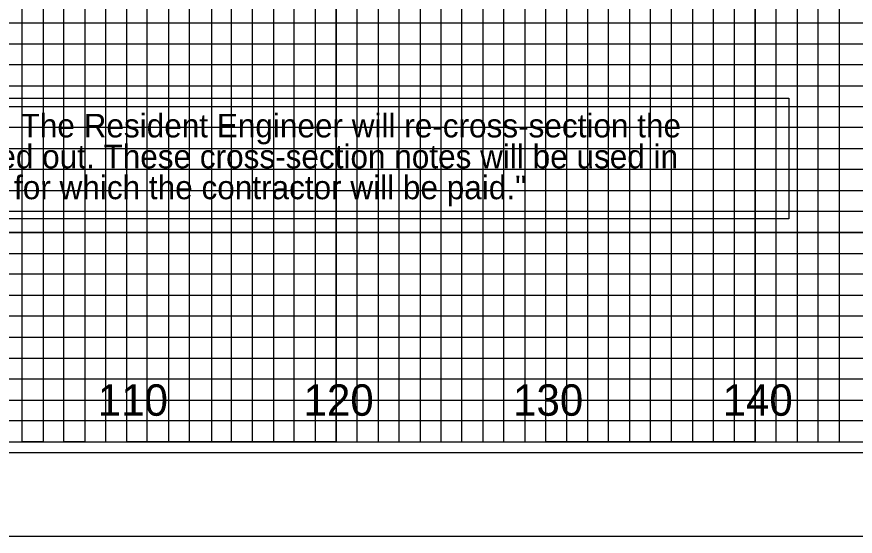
# Model space of a CAD drawing. Extents: x -13 to 371, y -5 to 215.
# Drawn here: x 264.75 to 304.77, y -4.5 to 20.29 of the extents above; entities that cross this region are included whole.
import ezdxf

# ---------------------------------------------------------------- set-up
doc = ezdxf.new("R2010")
doc.units = 0
for name, color, linetype in [('Exist Cross Section Cell', 7, 'Continuous'), ('Exist XS Center Line Elevation Label', 7, 'Continuous'), ('Exist XS Ground Line', 7, 'Continuous'), ('Prop CMT Pvmt Course 2', 7, 'Continuous'), ('Prop CMT Pvmt Course 3', 7, 'Continuous'), ('Prop CMT Pvmt Wedge Surface 2', 7, 'Continuous'), ('Prop CMT Pvmt Wedge Surface 3', 7, 'Continuous'), ('Prop CMT Shld Paved Course 2', 7, 'Continuous'), ('Prop CMT Shld Paved Course 3', 7, 'Continuous'), ('Prop CMT Slope Grass', 7, 'Continuous'), ('Prop CMT Subgrade Earthwork', 7, 'Continuous'), ('Scratch_Level_0', 7, 'Continuous')]:
    doc.layers.add(name, color=color, linetype=linetype)

msp = doc.modelspace()

# ---------------------------------------------------------------- linework, layer by layer
at = {"layer": 'Exist XS Center Line Elevation Label'}
for points in [[(264.99, 205), (264.99, 0), (275, 0), (275, 205)], [(285, 205), (285, 0), (295, 0), (295, 205)], [(0, 5), (320, 5), (320, 15), (0, 15)]]:
    msp.add_lwpolyline(points, dxfattribs=at)
at = {"layer": 'Exist XS Ground Line'}
for p, q in [((270, 0), (270, 205)), ((280, 205), (280, 0)), ((290, 0), (290, 205)), ((300, 205), (300, 0)), ((280, 0), (270, 0)), ((300, 0), (290, 0))]:
    msp.add_line(p, q, dxfattribs=at)
msp.add_lwpolyline([(0, 20), (320, 20), (320, 10), (0, 10)], dxfattribs=at)
at = {"layer": 'Prop CMT Pvmt Course 2'}
for p, q in [((270, 0), (270, 204.687)), ((280, 0), (280, 204.687)), ((290, 0), (290, 204.687)), ((300, 0), (300, 204.687)), ((0, 20), (320, 20)), ((0, 10), (320, 10))]:
    msp.add_line(p, q, dxfattribs=at)
at = {"layer": 'Prop CMT Pvmt Course 3'}
msp.add_line((-13.4, -4.5), (323.3, -4.5), dxfattribs=at)
at = {"layer": 'Prop CMT Pvmt Wedge Surface 2'}
msp.add_lwpolyline([(235.854, 16.408), (301.608, 16.408), (301.608, 10.642), (235.854, 10.642)], close=True, dxfattribs=at)
at = {"layer": 'Prop CMT Shld Paved Course 2'}
msp.add_lwpolyline([(-13.4, -4.5), (323.3, -4.5), (323.3, 214.5), (-13.4, 214.5)], close=True, dxfattribs=at)
at = {"layer": 'Prop CMT Shld Paved Course 3'}
msp.add_lwpolyline([(-10.8, -0.5), (322.4, -0.5), (322.4, 210.5), (-10.8, 210.5)], close=True, dxfattribs=at)
at = {"layer": 'Prop CMT Slope Grass'}
for p, q in [((266.01, 205), (266.01, 0)), ((267, 0), (267, 205)), ((268, 205), (268, 0)), ((269, 0), (269, 205)), ((266.01, 0), (265, 0)), ((268, 0), (267, 0))]:
    msp.add_line(p, q, dxfattribs=at)
for points in [[(270, 0), (270.98, 0), (270.98, 205), (272, 205), (272, 0)], [(272, 0), (273, 0), (273, 205), (274.05, 205), (274.05, 0)], [(275, 0), (276, 0), (276, 205), (277, 205), (277, 0)], [(277, 0), (278, 0), (278, 205), (279, 205), (279, 0)], [(280, 0), (281, 0), (281, 205), (282, 205), (282, 0)], [(282, 0), (283, 0), (283, 205), (284, 205), (284, 0)], [(285, 0), (286, 0), (286, 205), (287, 205), (287, 0)], [(287, 0), (288, 0), (288, 205), (289, 205), (289, 0)], [(290, 0), (291, 0), (291, 205), (292, 205), (292, 0)], [(292, 0), (293, 0), (293, 205), (294, 205), (294, 0)], [(295, 0), (296, 0), (296, 205), (297, 205), (297, 0)], [(297, 0), (298, 0), (298, 205), (299, 205), (299, 0)], [(300, 0), (301, 0), (301, 205), (302, 205), (302, 0)], [(302, 0), (303, 0), (303, 205), (304, 205), (304, 0)]]:
    msp.add_lwpolyline(points, dxfattribs=at)
at = {"layer": 'Prop CMT Subgrade Earthwork'}
msp.add_lwpolyline([(320, 210), (0, 210), (0, 0), (320, 0)], close=True, dxfattribs=at)
at = {"layer": 'Scratch_Level_0'}
for points in [[(0, 19), (320, 19), (320, 18), (0, 18)], [(0, 17), (320, 17), (320, 16), (0, 16)], [(0, 14), (320, 14), (320, 13), (0, 13)], [(0, 12), (320, 12), (320, 11), (0, 11)], [(0, 9), (320, 9), (320, 8), (0, 8)], [(0, 7), (320, 7), (320, 6), (0, 6)], [(0, 4), (320, 4), (320, 3), (0, 3)], [(0, 2), (320, 2), (320, 1), (0, 1)]]:
    msp.add_lwpolyline(points, dxfattribs=at)

# ---------------------------------------------------------------- texts
at = {"layer": 'Exist Cross Section Cell'}
for s, p in [('110', (268.624, 1.25)), ('120', (278.444, 1.25)), ('130', (288.444, 1.25)), ('140', (298.444, 1.25))]:
    msp.add_text(s, height=1.5, dxfattribs=at).set_placement(p)
at = {"layer": 'Prop CMT Pvmt Wedge Surface 3'}
for s, p in [('Note: "Quantities are approximate only. The Resident Engineer will re-cross-section the', (238.313, 14.535)), ('work accurately when the project is staked out. These cross-section notes will be used in', (237.285, 13.06)), ('computing the final quantities for which the contractor will be paid."', (244.72, 11.585))]:
    msp.add_text(s, height=1.125, dxfattribs=at).set_placement(p)

doc.saveas('drawing.dxf')
